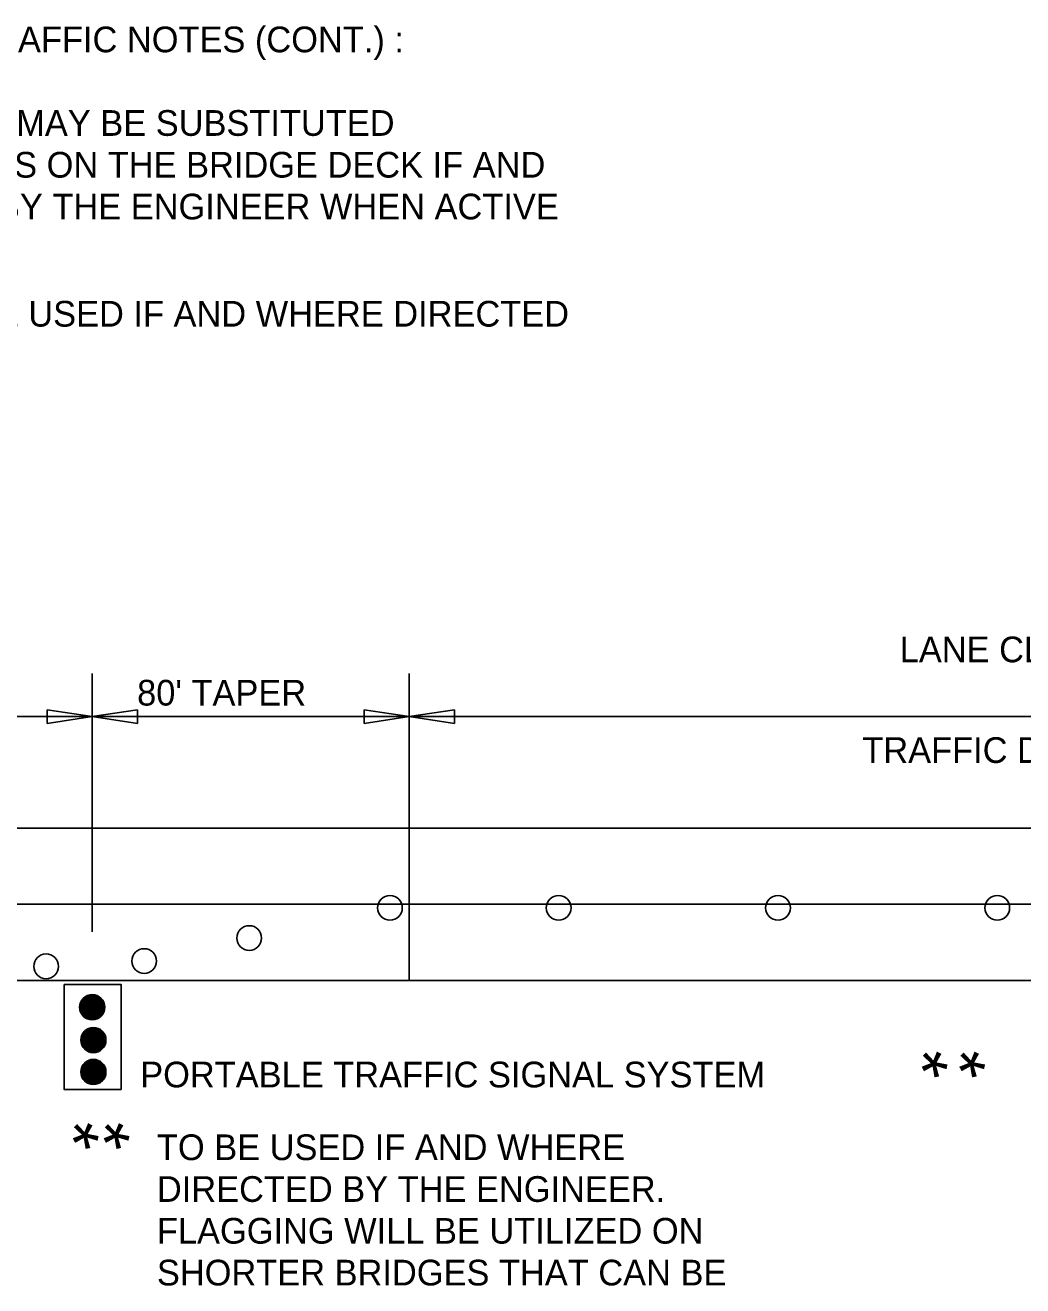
# Model space of a CAD drawing. Extents: x 1927831 to 1930787, y 596452 to 597699.
# Drawn here: x 1928639.7 to 1928872.4, y 597398.7 to 597692.9 of the extents above; entities that cross this region are included whole.
import ezdxf

# ---------------------------------------------------------------- set-up
doc = ezdxf.new("R2010")
doc.units = 0
doc.layers.add('Default', color=7, linetype='Continuous')
doc.layers.add('R_Border', color=7, linetype='Continuous')

msp = doc.modelspace()

# ---------------------------------------------------------------- linework, layer by layer
at = {"layer": 'Default'}
for p, q in [((1928655.37, 597541.61), (1928655.37, 597481.38)), ((1928729.31, 597541.61), (1928729.31, 597481.38)), ((1928604.7, 597531.57), (1928655.37, 597531.57)), ((1928644.83, 597529.98), (1928644.83, 597533.15)), ((1928644.83, 597533.15), (1928655.37, 597531.57)), ((1928655.37, 597531.57), (1928644.83, 597529.98)), ((1928655.37, 597531.57), (1928665.91, 597533.15)), ((1928655.37, 597531.57), (1928729.31, 597531.57)), ((1928665.91, 597529.98), (1928655.37, 597531.57)), ((1928665.91, 597533.15), (1928665.91, 597529.98)), ((1928718.76, 597529.98), (1928718.76, 597533.15)), ((1928718.76, 597533.15), (1928729.31, 597531.57)), ((1928729.31, 597531.57), (1928718.76, 597529.98)), ((1928729.31, 597531.57), (1928739.85, 597533.15)), ((1928739.85, 597529.98), (1928729.31, 597531.57)), ((1929173.7, 597531.57), (1928729.31, 597531.57)), ((1928739.85, 597533.15), (1928739.85, 597529.98)), ((1928729.31, 597510.51), (1928729.31, 597470.05)), ((1928044.85, 597505.58), (1929173.7, 597505.58)), ((1927908.3, 597487.79), (1929173.7, 597487.79)), ((1928044.85, 597470), (1929173.7, 597470)), ((1928652.41, 597463.61), (1928655.49, 597466.69)), ((1928652.41, 597463.79), (1928655.31, 597466.69)), ((1928652.42, 597463.98), (1928655.12, 597466.68)), ((1928652.43, 597463.44), (1928655.66, 597466.67)), ((1928652.44, 597464.18), (1928654.92, 597466.66)), ((1928652.45, 597463.28), (1928655.82, 597466.65)), ((1928652.48, 597463.13), (1928655.97, 597466.62)), ((1928652.49, 597464.41), (1928654.69, 597466.62)), ((1928652.51, 597462.99), (1928656.12, 597466.59)), ((1928652.55, 597462.85), (1928656.26, 597466.55)), ((1928652.56, 597464.66), (1928654.44, 597466.55)), ((1928652.6, 597462.71), (1928656.39, 597466.5)), ((1928652.65, 597462.58), (1928656.52, 597466.45)), ((1928652.67, 597464.95), (1928654.15, 597466.43)), ((1928652.71, 597462.46), (1928656.64, 597466.39)), ((1928652.77, 597462.34), (1928656.76, 597466.33)), ((1928652.84, 597462.23), (1928656.88, 597466.27)), ((1928652.89, 597465.35), (1928653.75, 597466.22)), ((1928652.91, 597462.11), (1928656.99, 597466.19)), ((1928652.98, 597462.01), (1928657.09, 597466.12)), ((1928653.06, 597461.91), (1928657.2, 597466.04)), ((1928653.14, 597461.81), (1928657.29, 597465.96)), ((1928653.23, 597461.71), (1928657.39, 597465.87)), ((1928653.32, 597461.62), (1928657.48, 597465.78)), ((1928653.41, 597461.54), (1928657.57, 597465.69)), ((1928653.51, 597461.45), (1928657.65, 597465.59)), ((1928653.61, 597461.38), (1928657.73, 597465.49)), ((1928653.72, 597461.3), (1928657.8, 597465.38)), ((1928653.83, 597461.23), (1928657.87, 597465.27)), ((1928653.95, 597461.16), (1928657.94, 597465.16)), ((1928654.07, 597461.1), (1928658, 597465.04)), ((1928654.19, 597461.05), (1928658.06, 597464.91)), ((1928654.32, 597460.99), (1928658.11, 597464.78)), ((1928654.45, 597460.95), (1928658.15, 597464.65)), ((1928654.59, 597460.91), (1928658.2, 597464.51)), ((1928654.74, 597460.87), (1928658.23, 597464.36)), ((1928654.89, 597460.84), (1928658.26, 597464.21)), ((1928655.05, 597460.82), (1928658.28, 597464.05)), ((1928655.22, 597460.81), (1928658.29, 597463.88)), ((1928655.4, 597460.81), (1928658.29, 597463.7)), ((1928655.59, 597460.82), (1928658.29, 597463.51)), ((1928655.79, 597460.84), (1928658.26, 597463.31)), ((1928656.02, 597460.88), (1928658.22, 597463.09)), ((1928656.27, 597460.95), (1928658.15, 597462.84)), ((1928656.56, 597461.07), (1928658.04, 597462.54)), ((1928656.96, 597461.28), (1928657.82, 597462.14)), ((1928652.68, 597455.95), (1928655.76, 597459.03)), ((1928652.68, 597456.13), (1928655.58, 597459.03)), ((1928652.69, 597456.32), (1928655.39, 597459.02)), ((1928652.7, 597455.79), (1928655.93, 597459.02)), ((1928652.71, 597456.53), (1928655.19, 597459)), ((1928652.72, 597455.63), (1928656.09, 597458.99)), ((1928652.75, 597455.47), (1928656.24, 597458.97)), ((1928652.76, 597456.75), (1928654.96, 597458.96)), ((1928652.78, 597455.33), (1928656.38, 597458.93)), ((1928652.82, 597455.19), (1928656.52, 597458.89)), ((1928652.83, 597457), (1928654.71, 597458.89)), ((1928652.87, 597455.05), (1928656.66, 597458.84)), ((1928652.92, 597454.92), (1928656.79, 597458.79)), ((1928652.94, 597457.29), (1928654.42, 597458.77)), ((1928652.98, 597454.8), (1928656.91, 597458.73)), ((1928653.04, 597454.68), (1928657.03, 597458.67)), ((1928653.11, 597454.57), (1928657.15, 597458.61)), ((1928653.16, 597457.69), (1928654.02, 597458.56)), ((1928653.18, 597454.46), (1928657.26, 597458.54)), ((1928653.25, 597454.35), (1928657.36, 597458.46)), ((1928653.33, 597454.25), (1928657.46, 597458.38)), ((1928653.41, 597454.15), (1928657.56, 597458.3)), ((1928653.5, 597454.05), (1928657.66, 597458.21)), ((1928653.59, 597453.96), (1928657.75, 597458.12)), ((1928653.68, 597453.88), (1928657.83, 597458.03)), ((1928653.78, 597453.79), (1928657.92, 597457.93)), ((1928653.88, 597453.72), (1928658, 597457.83)), ((1928653.99, 597453.64), (1928658.07, 597457.72)), ((1928654.1, 597453.57), (1928658.14, 597457.61)), ((1928654.22, 597453.51), (1928658.21, 597457.5)), ((1928654.34, 597453.44), (1928658.27, 597457.38)), ((1928654.46, 597453.39), (1928658.32, 597457.25)), ((1928654.59, 597453.34), (1928658.38, 597457.12)), ((1928654.72, 597453.29), (1928658.42, 597456.99)), ((1928654.86, 597453.25), (1928658.46, 597456.85)), ((1928655.01, 597453.21), (1928658.5, 597456.7)), ((1928655.16, 597453.18), (1928658.53, 597456.55)), ((1928655.32, 597453.16), (1928658.55, 597456.39)), ((1928655.49, 597453.15), (1928658.56, 597456.22)), ((1928655.67, 597453.15), (1928658.56, 597456.05)), ((1928655.86, 597453.16), (1928658.56, 597455.86)), ((1928656.06, 597453.18), (1928658.53, 597455.65)), ((1928656.28, 597453.22), (1928658.49, 597455.43)), ((1928656.54, 597453.29), (1928658.42, 597455.18)), ((1928656.83, 597453.41), (1928658.31, 597454.88)), ((1928657.23, 597453.62), (1928658.09, 597454.48)), ((1928652.68, 597448.61), (1928655.66, 597451.59)), ((1928652.68, 597448.8), (1928655.48, 597451.59)), ((1928652.69, 597448.44), (1928655.83, 597451.58)), ((1928652.7, 597448.99), (1928655.28, 597451.57)), ((1928652.71, 597448.27), (1928656, 597451.57)), ((1928652.73, 597448.12), (1928656.15, 597451.54)), ((1928652.73, 597449.21), (1928655.06, 597451.54)), ((1928652.76, 597447.97), (1928656.3, 597451.51)), ((1928652.79, 597449.45), (1928654.83, 597451.48)), ((1928652.8, 597447.83), (1928656.45, 597451.47)), ((1928652.84, 597447.69), (1928656.58, 597451.43)), ((1928652.88, 597449.72), (1928654.56, 597451.39)), ((1928652.89, 597447.56), (1928656.72, 597451.38)), ((1928652.95, 597447.43), (1928656.84, 597451.33)), ((1928653.01, 597447.31), (1928656.96, 597451.27)), ((1928653.04, 597450.05), (1928654.22, 597451.23)), ((1928653.07, 597447.19), (1928657.08, 597451.2)), ((1928653.14, 597447.08), (1928657.2, 597451.14)), ((1928653.21, 597446.97), (1928657.3, 597451.06)), ((1928653.29, 597446.86), (1928657.41, 597450.99)), ((1928653.37, 597446.76), (1928657.51, 597450.91)), ((1928653.45, 597446.67), (1928657.61, 597450.82)), ((1928653.54, 597446.57), (1928657.7, 597450.73)), ((1928653.63, 597446.49), (1928657.79, 597450.64)), ((1928653.73, 597446.4), (1928657.87, 597450.55)), ((1928653.83, 597446.32), (1928657.95, 597450.45)), ((1928653.93, 597446.24), (1928658.03, 597450.34)), ((1928654.04, 597446.17), (1928658.1, 597450.23)), ((1928654.15, 597446.1), (1928658.17, 597450.12)), ((1928654.27, 597446.04), (1928658.23, 597450)), ((1928654.39, 597445.98), (1928658.29, 597449.88)), ((1928654.65, 597445.87), (1928658.4, 597449.63)), ((1928654.78, 597445.83), (1928658.44, 597449.49)), ((1928654.93, 597445.79), (1928658.48, 597449.35)), ((1928655.07, 597445.76), (1928658.51, 597449.2)), ((1928655.23, 597445.73), (1928658.54, 597449.04)), ((1928655.39, 597445.72), (1928658.56, 597448.88)), ((1928655.57, 597445.71), (1928658.56, 597448.71)), ((1928655.75, 597445.71), (1928658.56, 597448.52)), ((1928655.95, 597445.73), (1928658.55, 597448.33)), ((1928656.16, 597445.76), (1928658.52, 597448.12)), ((1928656.39, 597445.81), (1928658.46, 597447.88)), ((1928656.66, 597445.9), (1928658.38, 597447.61)), ((1928656.99, 597446.04), (1928658.23, 597447.29)), ((1928657.56, 597446.44), (1928657.84, 597446.71))]:
    msp.add_line(p, q, dxfattribs=at)
msp.add_lwpolyline([(1928648.78, 597469.1), (1928662.07, 597469.1), (1928662.07, 597444.57), (1928648.78, 597444.57)], close=True, dxfattribs=at)
for centre, radius in [((1928724.81, 597486.95), 2.88), ((1928764.17, 597486.95), 2.88), ((1928815.34, 597486.95), 2.88), ((1928866.5, 597486.95), 2.88), ((1928691.97, 597479.91), 2.88), ((1928644.59, 597473.3), 2.88), ((1928667.47, 597474.54), 2.88), ((1928655.35, 597463.75), 2.94), ((1928655.62, 597456.09), 2.94), ((1928655.62, 597448.65), 2.94)]:
    msp.add_circle(centre, radius, dxfattribs=at)

# ---------------------------------------------------------------- texts
for s, height, p in [('LANE CLOSURE BRIDGE LENGTH + ROADWAY ', 5.9996, (1928843.74, 597544.26)), ("80' TAPER", 6, (1928665.82, 597534.16)), ("TRAFFIC DRUMS @ 40' O.C. IN CLOSED LANE", 5.9996, (1928835.01, 597520.77)), ('PORTABLE TRAFFIC SIGNAL SYSTEM', 6, (1928666.54, 597445.05))]:
    msp.add_text(s, height=height, rotation=360, dxfattribs=at).set_placement(p)
at = {"layer": 'R_Border'}
for s, height, rotation, p in [('MAINTENANCE OF TRAFFIC NOTES (CONT.) :', 6, 360, (1928553.34, 597686.62)), ('5. VERTICAL PANELS MAY BE SUBSTITUTED', 6, 360, (1928553.34, 597667.12)), ('  FOR TRAFFIC DRUMS ON THE BRIDGE DECK IF AND', 6, 360, (1928553.34, 597657.37)), ('  WHERE DIRECTED BY THE ENGINEER WHEN ACTIVE', 6, 360, (1928553.34, 597647.62)), ('6.  FLAGGING MAY BE USED IF AND WHERE DIRECTED', 6, 360, (1928553.05, 597622.6)), ('*', 12, 45, (1928855.76, 597442.1)), ('*', 12, 45, (1928864.53, 597442.1)), ('*', 12, 45, (1928657.72, 597425.4)), ('*', 12, 45, (1928664.91, 597425.4)), ('TO BE USED IF AND WHERE', 6, 360, (1928670.44, 597428.08)), ('DIRECTED BY THE ENGINEER.', 6, 360, (1928670.44, 597418.33)), ('FLAGGING WILL BE UTILIZED ON', 6, 360, (1928670.44, 597408.58)), ('SHORTER BRIDGES THAT CAN BE ', 6, 360, (1928670.44, 597398.83))]:
    msp.add_text(s, height=height, rotation=rotation, dxfattribs=at).set_placement(p)

doc.saveas('drawing.dxf')
